// Mitsubishi GX Works2 project: 实例训练（码垛）   PLC: FX3U/FX3UC

PROGRAM MAIN
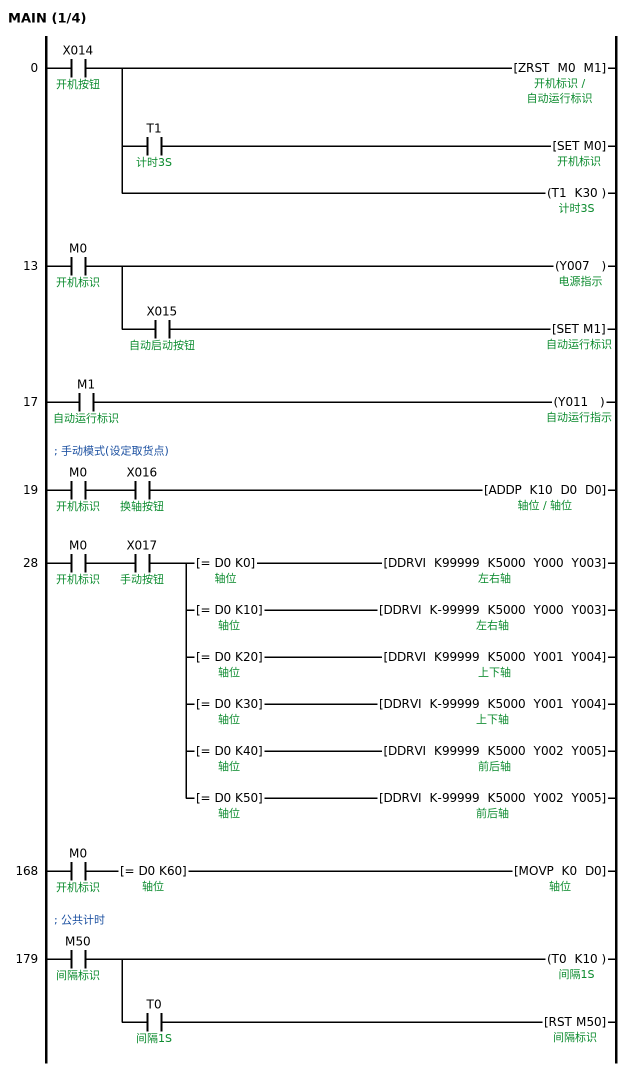
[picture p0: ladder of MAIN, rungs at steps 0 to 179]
0     LD      X014  ; 开机按钮
      ZRST    M0 M1  ; 开机标识 / 自动运行标识
        [note] X14点动关机
      MPS
      AND     T1  ; 计时3S
      SET     M0  ; 开机标识
        [note] X14长按3S开机
      MPP
      OUT     T1 K30  ; 计时3S
13    LD      M0  ; 开机标识
      OUT     Y007  ; 电源指示
      AND     X015  ; 自动启动按钮
      SET     M1  ; 自动运行标识
17    LD      M1  ; 自动运行标识
      OUT     Y011  ; 自动运行指示
; 手动模式(设定取货点)
19    LD      M0  ; 开机标识
      AND     X016  ; 换轴按钮
      ADDP    K10 D0 D0  ; 轴位
28    LD      M0  ; 开机标识
      AND     X017  ; 手动按钮
      MPS
      AND=    D0 K0  ; 轴位
      DDRVI   K99999 K5000 Y000 Y003  ; 左右轴
        [note] Y0轴左移
      MRD
      AND=    D0 K10  ; 轴位
      DDRVI   K-99999 K5000 Y000 Y003
        [note] Y0轴右移
      MRD
      AND=    D0 K20  ; 轴位
      DDRVI   K99999 K5000 Y001 Y004  ; 上下轴
        [note] Y1轴上移
      MRD
      AND=    D0 K30  ; 轴位
      DDRVI   K-99999 K5000 Y001 Y004
        [note] Y1轴下移
      MRD
      AND=    D0 K40  ; 轴位
      DDRVI   K99999 K5000 Y002 Y005  ; 前后轴
        [note] Y2轴前移
      MPP
      AND=    D0 K50  ; 轴位
      DDRVI   K-99999 K5000 Y002 Y005
        [note] Y2轴后移
168   LD      M0  ; 开机标识
      AND=    D0 K60  ; 轴位
      MOVP    K0 D0
; 公共计时
179   LD      M50  ; 间隔标识
      OUT     T0 K10  ; 间隔1S
      AND     T0  ; 间隔1S
      RST     M50  ; 间隔标识
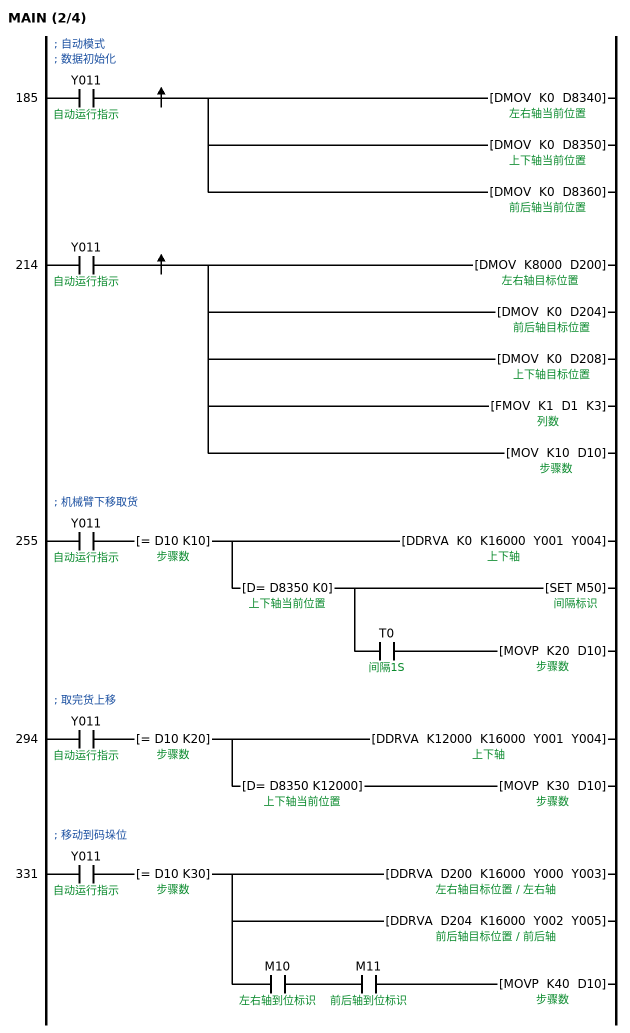
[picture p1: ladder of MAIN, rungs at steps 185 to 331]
; 自动模式
; 数据初始化
185   LD      Y011  ; 自动运行指示
      MEP
      DMOV    K0 D8340  ; 左右轴当前位置
      DMOV    K0 D8350  ; 上下轴当前位置
      DMOV    K0 D8360  ; 前后轴当前位置
214   LD      Y011  ; 自动运行指示
      MEP
      DMOV    K8000 D200  ; 左右轴目标位置
      DMOV    K0 D204  ; 前后轴目标位置
      DMOV    K0 D208  ; 上下轴目标位置
      FMOV    K1 D1 K3  ; 列数
      MOV     K10 D10  ; 步骤数
; 机械臂下移取货
255   LD      Y011  ; 自动运行指示
      AND=    D10 K10  ; 步骤数
      DDRVA   K0 K16000 Y001 Y004
      ANDD=   D8350 K0  ; 上下轴当前位置
      SET     M50  ; 间隔标识
      AND     T0  ; 间隔1S
      MOVP    K20 D10
; 取完货上移
294   LD      Y011  ; 自动运行指示
      AND=    D10 K20  ; 步骤数
      DDRVA   K12000 K16000 Y001 Y004
      ANDD=   D8350 K12000  ; 上下轴当前位置
      MOVP    K30 D10
; 移动到码垛位
331   LD      Y011  ; 自动运行指示
      AND=    D10 K30  ; 步骤数
      DDRVA   D200 K16000 Y000 Y003
      DDRVA   D204 K16000 Y002 Y005
      AND     M10  ; 左右轴到位标识
      AND     M11  ; 前后轴到位标识
      MOVP    K40 D10
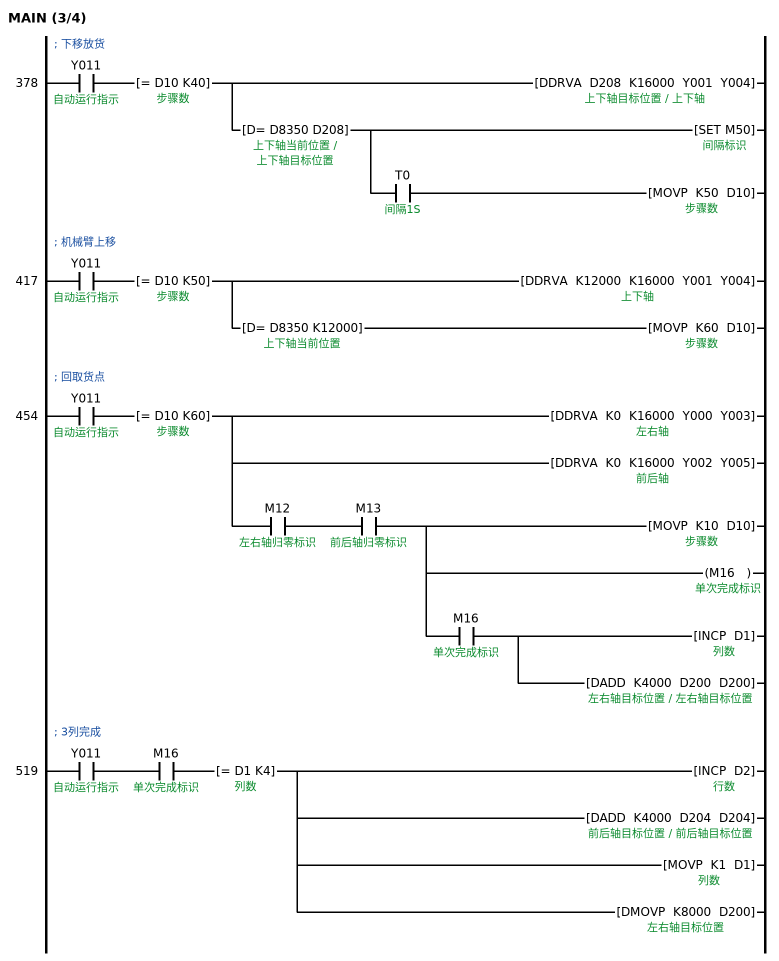
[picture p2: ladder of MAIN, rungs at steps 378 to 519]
; 下移放货
378   LD      Y011  ; 自动运行指示
      AND=    D10 K40  ; 步骤数
      DDRVA   D208 K16000 Y001 Y004
      ANDD=   D8350 D208  ; 上下轴当前位置 / 上下轴目标位置
      SET     M50  ; 间隔标识
      AND     T0  ; 间隔1S
      MOVP    K50 D10
; 机械臂上移
417   LD      Y011  ; 自动运行指示
      AND=    D10 K50  ; 步骤数
      DDRVA   K12000 K16000 Y001 Y004
      ANDD=   D8350 K12000  ; 上下轴当前位置
      MOVP    K60 D10
; 回取货点
454   LD      Y011  ; 自动运行指示
      AND=    D10 K60  ; 步骤数
      DDRVA   K0 K16000 Y000 Y003
      DDRVA   K0 K16000 Y002 Y005
      AND     M12  ; 左右轴归零标识
      AND     M13  ; 前后轴归零标识
      MOVP    K10 D10
      OUT     M16  ; 单次完成标识
      AND     M16  ; 单次完成标识
      INCP    D1
        [note] 单次完成列数自加一
      DADD    K4000 D200 D200
        [note] 单次完成左右轴+4000
; 3列完成
519   LD      Y011  ; 自动运行指示
      AND     M16  ; 单次完成标识
      AND=    D1 K4  ; 列数
      INCP    D2  ; 行数
        [note] 3列完成行数自加一
      DADD    K4000 D204 D204
        [note] 3列完成前后轴+4000
      MOVP    K1 D1
        [note] 3列完成列数归一
      DMOVP   K8000 D200
        [note] 3列完成左右轴回起始位
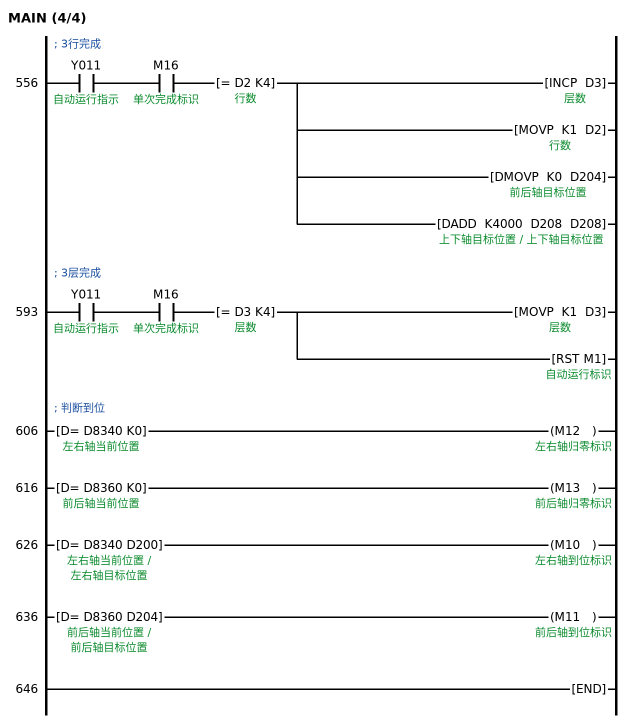
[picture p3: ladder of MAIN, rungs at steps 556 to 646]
; 3行完成
556   LD      Y011  ; 自动运行指示
      AND     M16  ; 单次完成标识
      AND=    D2 K4  ; 行数
      INCP    D3  ; 层数
        [note] 行完成层数自加一
      MOVP    K1 D2
        [note] 3行完成行数归一
      DMOVP   K0 D204
        [note] 3行完成前后轴回起始位
      DADD    K4000 D208 D208
        [note] 3行完成上下轴+4000
; 3层完成
593   LD      Y011  ; 自动运行指示
      AND     M16  ; 单次完成标识
      AND=    D3 K4  ; 层数
      MOVP    K1 D3
        [note] 3层完成层数归一
      RST     M1  ; 自动运行标识
; 判断到位
606   LDD=    D8340 K0  ; 左右轴当前位置
      OUT     M12  ; 左右轴归零标识
616   LDD=    D8360 K0  ; 前后轴当前位置
      OUT     M13  ; 前后轴归零标识
626   LDD=    D8340 D200  ; 左右轴当前位置 / 左右轴目标位置
      OUT     M10  ; 左右轴到位标识
636   LDD=    D8360 D204  ; 前后轴当前位置 / 前后轴目标位置
      OUT     M11  ; 前后轴到位标识
646   END
END_PROGRAM
